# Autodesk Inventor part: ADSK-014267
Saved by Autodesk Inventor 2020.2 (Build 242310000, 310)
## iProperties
Part Number: ADSK-014267
Material: Allgemein
Description: Framegenerator-Skeleton-Referenz
Document SubType Name: Modellieren
Designer: lutzd
Density: 1 g/cm^3
Appearance: Vorgabe
DocNumber: ADSK-014267
Folder: .
Dimensions: 0x0x0 mm
Mass: 0 kg
VLT_Material: Generisch
_SkeletonDoc: Frame Skeleton File
_Version: 15.0.0
Title: Gestellrahmenbauteil(e)
Author: lutzd
Revision Number: -
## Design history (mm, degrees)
sketch "Referenzrahmen"
node "Volumenkörper"
node "Flächenkörper"
